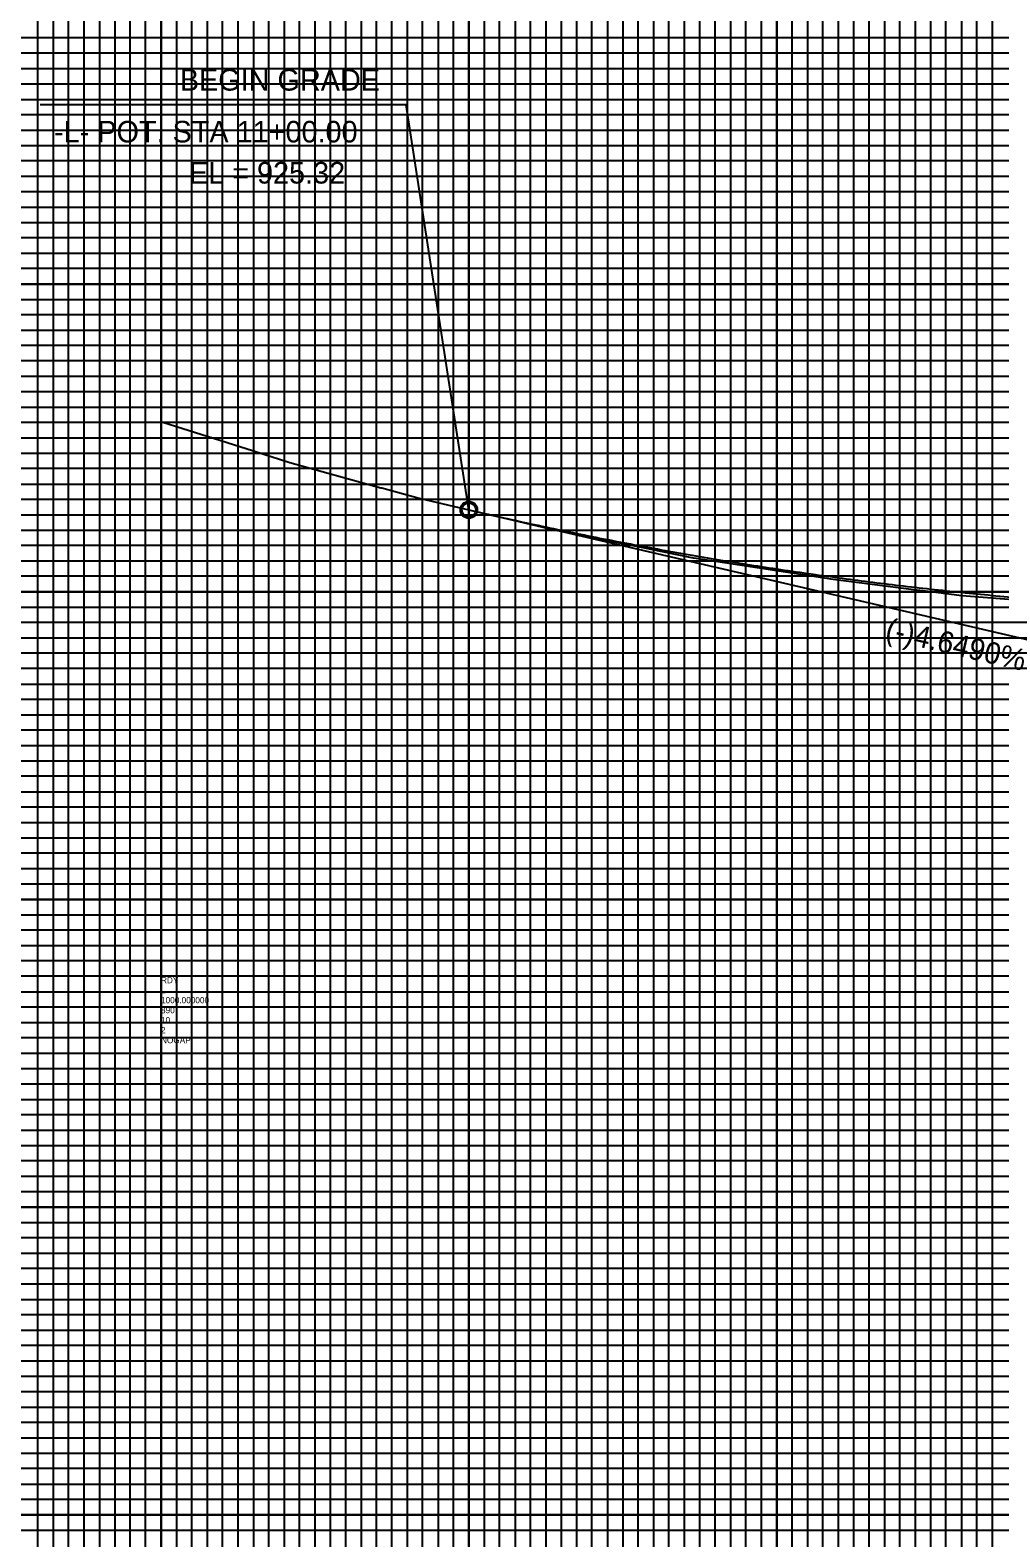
# Model space of a CAD drawing. Extents: x 573624 to 575507, y -53727 to -52273.
# Drawn here: x 574148.3 to 574463.3, y -53180.6 to -52690.6 of the extents above; entities that cross this region are included whole.
import ezdxf

# ---------------------------------------------------------------- set-up
doc = ezdxf.new("R2010")
doc.units = 0
for name, color, linetype in [('Exist Profile Cell', 7, 'Continuous'), ('Exist Vertical Profile Ground Line', 7, 'Continuous'), ('Prop Vertical Profile Curve Label', 7, 'Continuous'), ('Prop Vertical Profile Grade', 7, 'Continuous'), ('Prop Vertical Profile Grade Label', 7, 'Continuous'), ('Prop VPI Label', 7, 'Continuous'), ('Sheet DOT Grid CELL', 7, 'Continuous'), ('Sheet Profile Grid Major CELL', 7, 'Continuous'), ('Sheet Profile Grid Middle CELL', 7, 'Continuous'), ('Sheet Profile Grid Minor CELL', 7, 'Continuous')]:
    doc.layers.add(name, color=color, linetype=linetype)

msp = doc.modelspace()

# ---------------------------------------------------------------- linework, layer by layer
at = {"layer": 'Exist Profile Cell'}
for q in [(574190.78, -52773.09), (574877.61, -53023.09), (574190.78, -53023.09)]:
    msp.add_line((574190.78, -53023.09), q, dxfattribs=at)
at = {"layer": 'Exist Vertical Profile Ground Line'}
for p, q in [((574190.78, -52817.81), (574191.39, -52818.03)), ((574191.39, -52818.03), (574212.3, -52824.64)), ((574212.3, -52824.64), (574220.87, -52827.35)), ((574220.87, -52827.35), (574232.61, -52831.08)), ((574232.61, -52831.08), (574262.22, -52839.28)), ((574262.22, -52839.28), (574262.56, -52839.38)), ((574262.56, -52839.38), (574274.63, -52842.72)), ((574274.63, -52842.72), (574287.94, -52845.82)), ((574287.94, -52845.82), (574304.75, -52849.75)), ((574304.75, -52849.75), (574318.96, -52853.08)), ((574318.96, -52853.08), (574319.55, -52853.2)), ((574319.55, -52853.2), (574348.93, -52859.09)), ((574348.93, -52859.09), (574349.32, -52859.17)), ((574349.32, -52859.17), (574363.68, -52862.04)), ((574363.68, -52862.04), (574364.59, -52862.17)), ((574364.59, -52862.17), (574393.66, -52866.63)), ((574393.66, -52866.63), (574407.03, -52868.68)), ((574407.03, -52868.68), (574408.28, -52868.86)), ((574408.28, -52868.86), (574435.37, -52872.32)), ((574435.37, -52872.32), (574438.28, -52872.69)), ((574438.28, -52872.69), (574450.88, -52874.3)), ((574450.88, -52874.3), (574452.32, -52874.48)), ((574452.32, -52874.48), (574478.91, -52876.48))]:
    msp.add_line(p, q, dxfattribs=at)
at = {"layer": 'Prop Vertical Profile Curve Label'}
msp.add_circle((574290.78, -52846.49), 2.25, dxfattribs=at)
at = {"layer": 'Prop Vertical Profile Grade'}
msp.add_spline([(574290.78, -52846.49), (574300.78, -52848.78), (574310.78, -52850.98), (574320.78, -52853.1), (574330.78, -52855.14), (574340.78, -52857.1), (574350.78, -52858.98), (574360.78, -52860.78), (574370.78, -52862.49), (574380.78, -52864.13), (574390.78, -52865.68), (574400.78, -52867.15), (574410.78, -52868.54), (574420.78, -52869.85), (574430.78, -52871.08), (574440.78, -52872.22), (574450.78, -52873.29), (574460.78, -52874.27), (574470.78, -52875.18), (574480.78, -52876), (574490.78, -52876.74), (574500.78, -52877.4), (574510.78, -52877.98), (574520.78, -52878.47), (574530.78, -52878.89), (574540.78, -52879.22), (574550.78, -52879.48), (574560.78, -52879.65), (574570.78, -52879.74), (574580.78, -52879.75), (574590.78, -52879.68), (574600.78, -52879.52), (574610.78, -52879.29), (574620.78, -52878.98), (574630.78, -52878.58), (574640.78, -52878.1), (574650.78, -52877.54), (574660.78, -52876.9), (574670.78, -52876.18), (574680.78, -52875.38), (574690.78, -52874.49), (574700.78, -52873.53), (574710.78, -52872.48), (574720.78, -52871.35), (574730.78, -52870.14), (574740.78, -52868.85), (574750.78, -52867.48), (574760.78, -52866.03), (574770.78, -52864.5), (574780.78, -52862.88), (574790.78, -52861.19)], degree=3, dxfattribs=at)
at = {"layer": 'Prop VPI Label'}
for p, q in [((574270.46, -52714.85), (574151.5, -52714.85)), ((574290.78, -52846.49), (574270.46, -52714.85)), ((574290.78, -52846.49), (574538.1, -52903.98))]:
    msp.add_line(p, q, dxfattribs=at)
msp.add_circle((574290.78, -52846.49), 2.75, dxfattribs=at)
at = {"layer": 'Sheet DOT Grid CELL'}
for p, q in [((574190.78, -52298.09), (574190.78, -53323.09)), ((574240.78, -52298.09), (574240.78, -53323.09)), ((574290.78, -52298.09), (574290.78, -53323.09)), ((574340.78, -52298.09), (574340.78, -53323.09)), ((574390.78, -52298.09), (574390.78, -53323.09)), ((574440.78, -52298.09), (574440.78, -53323.09)), ((573790.78, -52723.09), (575290.78, -52723.09)), ((573790.78, -52773.09), (575290.78, -52773.09)), ((573790.78, -52823.09), (575290.78, -52823.09)), ((573790.78, -52873.09), (575290.78, -52873.09)), ((573790.78, -52923.09), (575290.78, -52923.09)), ((573790.78, -52973.09), (575290.78, -52973.09)), ((573790.78, -53023.09), (575290.78, -53023.09)), ((573790.78, -53073.09), (575290.78, -53073.09)), ((573790.78, -53123.09), (575290.78, -53123.09)), ((573790.78, -53173.09), (575290.78, -53173.09))]:
    msp.add_line(p, q, dxfattribs=at)
at = {"layer": 'Sheet Profile Grid Major CELL'}
for points in [[(574190.78, -53323.09), (574190.78, -52298.09), (574240.78, -52298.09), (574240.78, -53323.09)], [(574290.78, -53323.09), (574290.78, -52298.09), (574340.78, -52298.09), (574340.78, -53323.09)], [(574390.78, -53323.09), (574390.78, -52298.09), (574440.78, -52298.09), (574440.78, -53323.09)], [(575290.78, -52773.09), (573790.78, -52773.09), (573790.78, -52723.09), (575290.78, -52723.09)], [(575290.78, -52873.09), (573790.78, -52873.09), (573790.78, -52823.09), (575290.78, -52823.09)], [(575290.78, -52973.09), (573790.78, -52973.09), (573790.78, -52923.09), (575290.78, -52923.09)], [(575290.78, -53073.09), (573790.78, -53073.09), (573790.78, -53023.09), (575290.78, -53023.09)], [(575290.78, -53173.09), (573790.78, -53173.09), (573790.78, -53123.09), (575290.78, -53123.09)]]:
    msp.add_lwpolyline(points, dxfattribs=at)
at = {"layer": 'Sheet Profile Grid Middle CELL'}
for points in [[(574165.78, -53323.09), (574165.78, -52298.09), (574215.78, -52298.09), (574215.78, -53323.09)], [(574265.78, -53323.09), (574265.78, -52298.09), (574315.78, -52298.09), (574315.78, -53323.09)], [(574365.78, -53323.09), (574365.78, -52298.09), (574415.78, -52298.09), (574415.78, -53323.09)], [(575290.78, -52698.09), (573790.78, -52698.09), (573790.78, -52748.09), (575290.78, -52748.09)], [(575290.78, -52798.09), (573790.78, -52798.09), (573790.78, -52848.09), (575290.78, -52848.09)], [(575290.78, -52898.09), (573790.78, -52898.09), (573790.78, -52948.09), (575290.78, -52948.09)], [(575290.78, -52998.09), (573790.78, -52998.09), (573790.78, -53048.09), (575290.78, -53048.09)], [(575290.78, -53098.09), (573790.78, -53098.09), (573790.78, -53148.09), (575290.78, -53148.09)]]:
    msp.add_lwpolyline(points, dxfattribs=at)
at = {"layer": 'Sheet Profile Grid Minor CELL'}
for points in [[(574150.78, -53323.09), (574150.78, -52298.09), (574155.78, -52298.09), (574155.78, -53323.09)], [(574160.78, -53323.09), (574160.78, -52298.09), (574170.78, -52298.09), (574170.78, -53323.09)], [(574175.78, -52298.09), (574175.78, -53323.09), (574180.78, -53323.09), (574180.78, -52298.09)], [(574175.78, -52298.69), (574175.78, -53323.09), (574180.78, -53323.09), (574180.78, -52298.69)], [(574185.78, -53323.09), (574185.78, -52298.09), (574195.78, -52298.09), (574195.78, -53323.09)], [(574200.78, -53323.09), (574200.78, -52298.09), (574205.78, -52298.09), (574205.78, -53323.09)], [(574210.78, -53323.09), (574210.78, -52298.09), (574220.78, -52298.09), (574220.78, -53323.09)], [(574225.78, -53323.09), (574225.78, -52298.09), (574230.78, -52298.09), (574230.78, -53323.09)], [(574235.78, -53323.09), (574235.78, -52298.09), (574245.78, -52298.09), (574245.78, -53323.09)], [(574250.78, -53323.09), (574250.78, -52298.09), (574255.78, -52298.09), (574255.78, -53323.09)], [(574260.78, -53323.09), (574260.78, -52298.09), (574270.78, -52298.09), (574270.78, -53323.09)], [(574275.78, -53323.09), (574275.78, -52298.09), (574280.78, -52298.09), (574280.78, -53323.09)], [(574285.78, -53323.09), (574285.78, -52298.09), (574295.78, -52298.09), (574295.78, -53323.09)], [(574300.78, -53323.09), (574300.78, -52298.09), (574305.78, -52298.09), (574305.78, -53323.09)], [(574310.78, -53323.09), (574310.78, -52298.09), (574320.78, -52298.09), (574320.78, -53323.09)], [(574325.78, -52298.09), (574325.78, -53323.09), (574330.78, -53323.09), (574330.78, -52298.09), (574335.78, -52298.09), (574335.78, -53323.09), (574345.78, -53323.09), (574345.78, -52298.09), (574350.78, -52298.09), (574350.78, -53323.09), (574355.78, -53323.09), (574355.78, -52298.09), (574360.78, -52298.09), (574360.78, -53323.09)], [(574370.78, -53323.09), (574370.78, -52298.09), (574375.78, -52298.09), (574375.78, -53323.09)], [(574380.78, -53323.09), (574380.78, -52298.09), (574385.78, -52298.09), (574385.78, -53323.09)], [(574395.78, -53323.09), (574395.78, -52298.09), (574400.78, -52298.09), (574400.78, -53323.09)], [(574405.78, -53323.09), (574405.78, -52298.09), (574410.78, -52298.09), (574410.78, -53323.09)], [(574420.78, -53323.09), (574420.78, -52298.09), (574425.78, -52298.09), (574425.78, -53323.09)], [(574430.78, -53323.09), (574430.78, -52298.09), (574435.78, -52298.09), (574435.78, -53323.09)], [(574445.78, -53323.09), (574445.78, -52298.09), (574450.78, -52298.09), (574450.78, -53323.09)], [(574455.78, -53323.09), (574455.78, -52298.09), (574460.78, -52298.09), (574460.78, -53323.09)], [(575240.78, -52693.09), (573840.78, -52693.09), (573840.78, -52703.09), (575240.78, -52703.09)], [(575240.78, -52708.09), (573840.78, -52708.09), (573840.78, -52713.09), (575240.78, -52713.09)], [(575240.78, -52718.09), (573840.78, -52718.09), (573840.78, -52728.09), (575240.78, -52728.09)], [(575240.78, -52733.09), (573840.78, -52733.09), (573840.78, -52738.09), (575240.78, -52738.09)], [(575240.78, -52743.09), (573840.78, -52743.09), (573840.78, -52753.09), (575240.78, -52753.09)], [(575240.78, -52758.09), (573840.78, -52758.09), (573840.78, -52763.09), (575240.78, -52763.09)], [(575240.78, -52768.09), (573840.78, -52768.09), (573840.78, -52778.09), (575240.78, -52778.09)], [(575240.78, -52783.09), (573840.78, -52783.09), (573840.78, -52788.09), (575240.78, -52788.09)], [(575240.78, -52793.09), (573840.78, -52793.09), (573840.78, -52803.09), (575240.78, -52803.09)], [(575240.78, -52808.09), (573840.78, -52808.09), (573840.78, -52813.09), (575240.78, -52813.09)], [(575240.78, -52818.09), (573840.78, -52818.09)], [(573840.78, -52828.09), (575240.78, -52828.09)], [(575240.78, -52833.09), (573840.78, -52833.09), (573840.78, -52838.09), (575240.78, -52838.09)], [(575240.78, -52843.09), (573840.78, -52843.09), (573840.78, -52853.09), (575240.78, -52853.09)], [(575240.78, -52858.09), (573840.78, -52858.09), (573840.78, -52863.09), (575240.78, -52863.09)], [(575240.78, -52868.09), (573840.78, -52868.09), (573840.78, -52878.09), (575240.78, -52878.09)], [(575240.78, -52883.09), (573840.78, -52883.09), (573840.78, -52888.09), (575240.78, -52888.09)], [(575240.78, -52893.09), (573840.78, -52893.09), (573840.78, -52903.09), (575240.78, -52903.09)], [(575240.78, -52908.09), (573840.78, -52908.09), (573840.78, -52913.09), (575240.78, -52913.09)], [(575240.78, -52918.09), (573840.78, -52918.09), (573840.78, -52928.09), (575240.78, -52928.09)], [(575240.78, -52933.09), (573840.78, -52933.09), (573840.78, -52938.09), (575240.78, -52938.09)], [(575240.78, -52943.09), (573840.78, -52943.09), (573840.78, -52953.09), (575240.78, -52953.09)], [(575240.78, -52958.09), (573840.78, -52958.09), (573840.78, -52963.09), (575240.78, -52963.09)], [(575240.78, -52968.09), (573840.78, -52968.09), (573840.78, -52978.09), (575240.78, -52978.09)], [(575240.78, -52983.09), (573840.78, -52983.09), (573840.78, -52988.09), (575240.78, -52988.09)], [(575240.78, -52993.09), (573840.78, -52993.09), (573840.78, -53003.09), (575240.78, -53003.09)], [(575240.78, -53008.09), (573840.78, -53008.09), (573840.78, -53013.09), (575240.78, -53013.09)], [(575240.78, -53018.09), (573840.78, -53018.09), (573840.78, -53028.09), (575240.78, -53028.09)], [(575240.78, -53033.09), (573840.78, -53033.09), (573840.78, -53038.09), (575240.78, -53038.09)], [(575240.78, -53043.09), (573840.78, -53043.09), (573840.78, -53053.09), (575240.78, -53053.09)], [(575240.78, -53058.09), (573840.78, -53058.09), (573840.78, -53063.09), (575240.78, -53063.09)], [(575240.78, -53068.09), (573840.78, -53068.09), (573840.78, -53078.09), (575240.78, -53078.09)], [(575240.78, -53083.09), (573840.78, -53083.09), (573840.78, -53088.09), (575240.78, -53088.09)], [(575240.78, -53093.09), (573840.78, -53093.09), (573840.78, -53103.09), (575240.78, -53103.09)], [(575240.78, -53108.09), (573840.78, -53108.09), (573840.78, -53113.09), (575240.78, -53113.09)], [(575240.78, -53118.09), (573840.78, -53118.09)], [(573840.78, -53128.09), (575240.78, -53128.09)], [(575240.78, -53133.09), (573840.78, -53133.09), (573840.78, -53138.09), (575240.78, -53138.09)], [(575240.78, -53143.09), (573840.78, -53143.09)], [(573840.78, -53153.09), (575240.78, -53153.09)], [(575240.78, -53158.09), (573840.78, -53158.09), (573840.78, -53163.09), (575240.78, -53163.09)], [(575240.78, -53168.09), (573840.78, -53168.09), (573840.78, -53178.09), (575240.78, -53178.09)]]:
    msp.add_lwpolyline(points, dxfattribs=at)

# ---------------------------------------------------------------- texts
at = {"layer": 'Exist Profile Cell'}
for s, p in [('RDY', (574190.78, -53000.34)), ('L', (574190.78, -53003.59)), ('890', (574190.78, -53010.09)), ('1000.000000', (574190.78, -53006.84)), ('10', (574190.78, -53013.34)), ('2', (574190.78, -53016.59)), ('NOGAP', (574190.78, -53019.84))]:
    msp.add_text(s, height=2, dxfattribs=at).set_placement(p)
at = {"layer": 'Prop Vertical Profile Grade Label'}
msp.add_text('(-)4.6490%', height=7, rotation=346.9139, dxfattribs=at).set_placement((574425.71, -52888.41))
at = {"layer": 'Prop VPI Label'}
for s, p in [('BEGIN GRADE', (574196.9, -52710.23)), ('-L- POT. STA 11+00.00', (574156.05, -52727.08)), ('EL = 925.32', (574199.85, -52740.44))]:
    msp.add_text(s, height=7, dxfattribs=at).set_placement(p)

doc.saveas('drawing.dxf')
